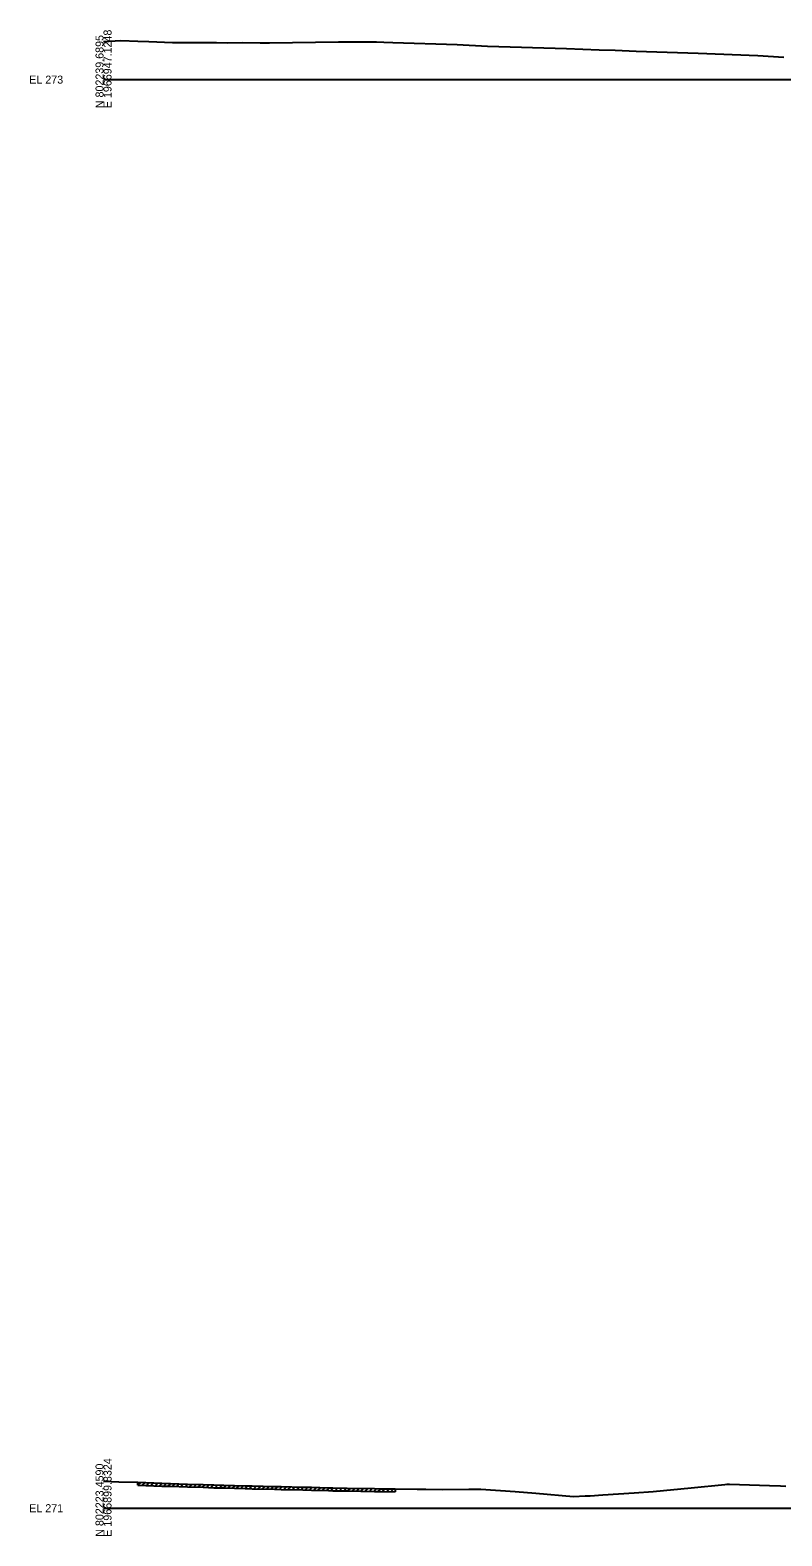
# Model space of a CAD drawing. Extents: x -4026 to 9638, y -10 to 19609.
# Drawn here: x 3974 to 4237, y 7490 to 8017 of the extents above; entities that cross this region are included whole.
import ezdxf

# ---------------------------------------------------------------- set-up
doc = ezdxf.new("R2010")
doc.units = 0
for name, color, linetype in [('Default', 7, 'Continuous'), ('RD_GPK_XS_Cell', 7, 'Continuous'), ('RD_XS_ExGround', 7, 'Continuous'), ('RD_XS_ExPaveRet', 7, 'Continuous')]:
    doc.layers.add(name, color=color, linetype=linetype)

msp = doc.modelspace()

# ---------------------------------------------------------------- linework, layer by layer
at = {"layer": 'RD_GPK_XS_Cell'}
for p, q in [((4000, 8000), (4350, 8000)), ((4000, 7500), (4350, 7500))]:
    msp.add_line(p, q, dxfattribs=at)
at = {"layer": 'RD_XS_ExGround'}
for points in [[(4000, 8013.36), (4006.02, 8013.63), (4012.05, 8013.49), (4015.81, 8013.34), (4024.12, 8013.02), (4039.57, 8012.95), (4043.34, 8012.91), (4048.59, 8013.04), (4054.84, 8012.88), (4058.1, 8012.92), (4082.19, 8013.21), (4095.54, 8013.17), (4098.15, 8013.16), (4101.27, 8012.94), (4123.73, 8012.24), (4134.42, 8011.67), (4162, 8010.84), (4173.44, 8010.42), (4179.05, 8010.27), (4186.39, 8009.99), (4208.18, 8009.22), (4229.05, 8008.42), (4238.06, 8007.83)], [(4000, 7509.48), (4005.39, 7509.28), (4011.64, 7509.07), (4012.06, 7509.06), (4020.36, 7508.76), (4023.44, 7508.66), (4029.36, 7508.46), (4034.85, 7508.3), (4038.63, 7508.18), (4041.13, 7508.11), (4042.14, 7508.08), (4049.61, 7507.88), (4052, 7507.82), (4059.88, 7507.62), (4062.18, 7507.56), (4069.74, 7507.38), (4072.75, 7507.3), (4078.76, 7507.17), (4080.25, 7507.13), (4085.25, 7507.03), (4094.9, 7506.85), (4096.93, 7506.81), (4102.13, 7506.73), (4109.83, 7506.61), (4112.81, 7506.61), (4118.48, 7506.58), (4127.81, 7506.61), (4129.53, 7506.61), (4132.06, 7506.62), (4144.12, 7505.79), (4151.3, 7505.24), (4164.52, 7504.11), (4168.61, 7504.29), (4170.32, 7504.37), (4174.79, 7504.69), (4185.68, 7505.38), (4192.41, 7505.89), (4205.64, 7507.09), (4217.48, 7508.31), (4218.14, 7508.39), (4219.13, 7508.38), (4233.04, 7507.99), (4236.99, 7507.82), (4238.85, 7507.72)]]:
    msp.add_lwpolyline(points, dxfattribs=at)
at = {"layer": 'RD_XS_ExPaveRet'}
for p, q in [((4012.06, 7508.06), (4012.06, 7509.06)), ((4012.06, 7508.06), (4013.03, 7509.02)), ((4012.06, 7508.06), (4020.36, 7507.76)), ((4013.56, 7508), (4014.53, 7508.97)), ((4015.06, 7507.95), (4016.03, 7508.92)), ((4016.56, 7507.9), (4017.53, 7508.86)), ((4018.06, 7507.85), (4019.03, 7508.81)), ((4019.56, 7507.79), (4020.53, 7508.76)), ((4020.36, 7507.76), (4023.44, 7507.66)), ((4021.06, 7507.74), (4022.03, 7508.71)), ((4022.56, 7507.69), (4023.53, 7508.65)), ((4023.44, 7507.66), (4029.36, 7507.46)), ((4024.06, 7507.64), (4025.03, 7508.6)), ((4025.56, 7507.59), (4026.53, 7508.55)), ((4027.06, 7507.54), (4028.03, 7508.51)), ((4028.56, 7507.49), (4029.53, 7508.46)), ((4029.36, 7507.46), (4034.85, 7507.3)), ((4030.06, 7507.44), (4031.03, 7508.41)), ((4031.56, 7507.39), (4032.53, 7508.37)), ((4033.06, 7507.35), (4034.03, 7508.32)), ((4034.56, 7507.3), (4035.53, 7508.28)), ((4034.85, 7507.3), (4038.63, 7507.18)), ((4036.06, 7507.26), (4037.03, 7508.23)), ((4037.56, 7507.21), (4038.53, 7508.18)), ((4038.63, 7507.18), (4041.13, 7507.11)), ((4039.06, 7507.17), (4040.04, 7508.14)), ((4040.56, 7507.13), (4041.54, 7508.1)), ((4041.13, 7507.11), (4042.14, 7507.08)), ((4042.06, 7507.09), (4043.04, 7508.06)), ((4042.14, 7507.08), (4049.61, 7506.88)), ((4043.56, 7507.05), (4044.54, 7508.02)), ((4045.06, 7507.01), (4046.04, 7507.98)), ((4046.56, 7506.96), (4047.54, 7507.94)), ((4048.06, 7506.92), (4049.04, 7507.9)), ((4049.56, 7506.88), (4050.54, 7507.86)), ((4049.61, 7506.88), (4052, 7506.82)), ((4051.06, 7506.84), (4052.04, 7507.82)), ((4052, 7506.82), (4059.88, 7506.62)), ((4052.56, 7506.8), (4053.54, 7507.78)), ((4054.06, 7506.76), (4055.04, 7507.74)), ((4055.56, 7506.73), (4056.54, 7507.7)), ((4057.06, 7506.69), (4058.04, 7507.66)), ((4058.56, 7506.65), (4059.54, 7507.62)), ((4059.88, 7506.62), (4062.18, 7506.56)), ((4060.06, 7506.61), (4061.04, 7507.59)), ((4061.56, 7506.57), (4062.54, 7507.55)), ((4062.18, 7506.56), (4069.74, 7506.38)), ((4063.06, 7506.54), (4064.04, 7507.51)), ((4064.56, 7506.5), (4065.54, 7507.48)), ((4066.06, 7506.46), (4067.04, 7507.44)), ((4067.56, 7506.43), (4068.54, 7507.4)), ((4069.06, 7506.39), (4070.04, 7507.37)), ((4069.74, 7506.38), (4072.75, 7506.3)), ((4070.56, 7506.36), (4071.54, 7507.33)), ((4072.06, 7506.32), (4073.04, 7507.3)), ((4072.75, 7506.3), (4078.76, 7506.17)), ((4073.56, 7506.28), (4074.54, 7507.26)), ((4075.06, 7506.25), (4076.04, 7507.23)), ((4076.56, 7506.22), (4077.54, 7507.19)), ((4078.06, 7506.18), (4079.04, 7507.16)), ((4078.76, 7506.17), (4080.25, 7506.13)), ((4079.56, 7506.15), (4080.54, 7507.13)), ((4080.25, 7506.13), (4085.25, 7506.03)), ((4081.06, 7506.12), (4082.04, 7507.1)), ((4082.56, 7506.09), (4083.54, 7507.07)), ((4084.06, 7506.06), (4085.04, 7507.04)), ((4085.25, 7506.03), (4094.9, 7505.85)), ((4085.56, 7506.03), (4086.54, 7507.01)), ((4087.06, 7506), (4088.04, 7506.98)), ((4088.56, 7505.97), (4089.54, 7506.95)), ((4090.06, 7505.94), (4091.04, 7506.92)), ((4091.56, 7505.91), (4092.54, 7506.89)), ((4093.06, 7505.88), (4094.04, 7506.86)), ((4094.56, 7505.85), (4095.54, 7506.84)), ((4094.9, 7505.85), (4096.93, 7505.81)), ((4096.06, 7505.83), (4097.04, 7506.81)), ((4096.93, 7505.81), (4102.13, 7505.73)), ((4097.56, 7505.8), (4098.55, 7506.79)), ((4099.06, 7505.78), (4100.05, 7506.76)), ((4100.56, 7505.75), (4101.55, 7506.74)), ((4102.13, 7506.73), (4102.13, 7505.73))]:
    msp.add_line(p, q, dxfattribs=at)

# ---------------------------------------------------------------- texts
at = {"layer": 'Default'}
for p in [(4000, 8000), (4000, 7500)]:
    msp.add_text('-', height=0.0001, dxfattribs=at).set_placement(p)
at = {"layer": 'RD_GPK_XS_Cell'}
for s, p in [('E 1966947.1248', (4002.8, 7990)), ('N 802239.6895', (4000, 7990)), ('N 802223.4590', (4000, 7490)), ('E 1966899.8324', (4002.8, 7490))]:
    msp.add_text(s, height=2.8, rotation=90, dxfattribs=at).set_placement(p)
for s, p in [('EL 273', (3974, 7998.6)), ('EL 271', (3974, 7498.6))]:
    msp.add_text(s, height=2.8, dxfattribs=at).set_placement(p)

doc.saveas('drawing.dxf')
